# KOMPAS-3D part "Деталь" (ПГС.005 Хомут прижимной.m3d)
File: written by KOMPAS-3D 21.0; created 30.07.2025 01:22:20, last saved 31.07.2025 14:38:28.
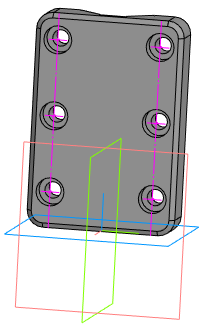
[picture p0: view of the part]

Document properties: Автор: rinat.gaysin.00@bk.ru; Полное имя файла: C:\Users\User\Desktop\ПЕРСПЕКТИВА кд\Модель\ПГС.005 Хомут прижимной.m3d

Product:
- Part/product: Деталь
    Масса: 0.19206

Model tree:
1. Эскиз:1
2. Элемент выдавливания:1
     Расстояние 1 = 65
3. Скругление:1  (with: Элемент выдавливания:1)
     Радиус = 5
4. Фаска:1  (with: Элемент выдавливания:1)
     Угол = 45; Длина 1 = 1.5; Длина 2 = 1.5
5. Эскиз:2  (with: Элемент выдавливания:1, Фаска:1)
6. Отверстие:1  (with: Элемент выдавливания:1, Фаска:1)
     Глубина выреза = 14; Диаметр отверстия = 5; Угол конуса дна = 118; Расстояние 1 = -5.4; Расстояние 2 = 55.5; Диаметр цековки = 8.5; Глубина цековки = 5
7. Массив по точкам:1
8. Экземпляр ( 1 )  (with: Отверстие:1, Эскиз:2)
9. Экземпляр ( 4 )  (with: Отверстие:1, Эскиз:2)
10. Экземпляр ( 3 )  (with: Отверстие:1, Эскиз:2)
11. Экземпляр ( 5 )  (with: Отверстие:1, Эскиз:2)
12. Экземпляр ( 2 )  (with: Отверстие:1, Эскиз:2)  (labels: v99_v263; v99_v264)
